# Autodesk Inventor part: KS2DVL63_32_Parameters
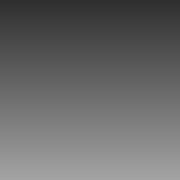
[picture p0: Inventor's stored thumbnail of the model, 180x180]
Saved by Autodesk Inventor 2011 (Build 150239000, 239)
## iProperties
Created: 2010-10
Document SubType Name: Modeling
Designer: TB
Density: 1 g/cm^3
Slaglengde: 100,000 mm
Vinkel_Minusport: 0.00 deg
Forlengelse_rør: 0.000 mm
Minusport2: 180.00 deg
Author: TB
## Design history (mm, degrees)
other parameters: "Slaglengde" = 100 [user parameter], "Forlengelse_rør" = 0 [user parameter], "Vinkel_Minusport" = 0 deg [user parameter], "Minusport2" = 180 deg [user parameter]
